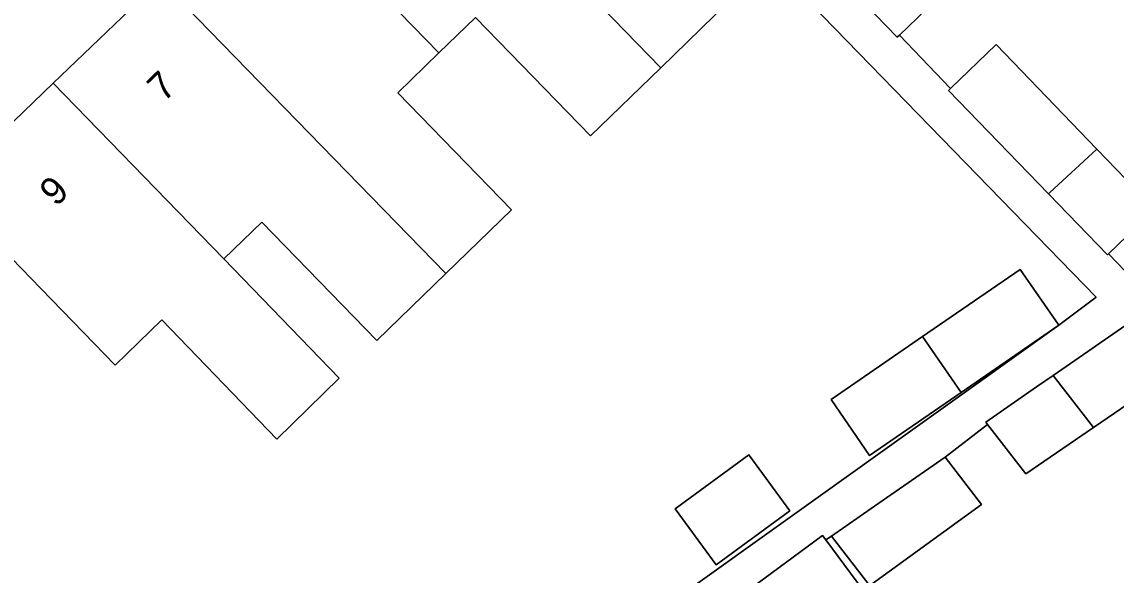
# Model space of a CAD drawing. Extents: x 159716 to 160783, y 383290 to 384031.
# Drawn here: x 160373.24 to 160412.95, y 383590.97 to 383611.06 of the extents above; entities that cross this region are included whole.
import ezdxf

# ---------------------------------------------------------------- set-up
doc = ezdxf.new("R2010")
doc.units = 0
for name, color, linetype in [('IMGEO_Erf', 7, 'Continuous'), ('IMGEO_Pand', 7, 'Continuous'), ('IMGEO_Pand_nummerreeks', 7, 'Continuous'), ('IMGEO_Voetpad_open', 7, 'Continuous')]:
    doc.layers.add(name, color=color, linetype=linetype)

msp = doc.modelspace()

# ---------------------------------------------------------------- linework, layer by layer
at = {"layer": 'IMGEO_Erf'}
for points in [[(160413.12, 383633.736), (160408.508, 383629.478), (160407.851, 383630.189), (160406.37, 383631.793), (160404.46, 383633.863), (160409.273, 383638.305), (160407.196, 383640.387), (160391.191, 383625.117), (160395.117, 383621.009), (160396.709, 383622.544), (160398.982, 383620.189), (160397.38, 383618.642), (160398.946, 383617.003), (160400.557, 383618.557), (160404.398, 383614.578), (160406.727, 383612.166), (160405.085, 383610.58), (160406.942, 383608.637), (160408.595, 383610.231), (160412.256, 383606.439), (160414.358, 383604.26), (160412.676, 383602.637), (160413.594, 383601.677)], [(160382.805, 383579.972), (160410.87, 383600.045), (160412.23, 383601.067), (160396.267, 383617.485), (160394.739, 383615.995), (160398.86, 383611.757), (160396.431, 383609.395), (160393.88, 383606.915), (160389.7, 383611.214), (160388.378, 383609.929), (160386.887, 383608.478), (160391.009, 383604.238), (160388.628, 383601.923), (160386.126, 383599.49), (160381.946, 383603.789), (160380.575, 383602.456), (160384.759, 383598.117), (160382.49, 383595.911), (160378.318, 383600.238), (160376.63, 383598.596), (160373.926, 383601.377), (160370.406, 383605.011)], [(160414.882, 383598.21), (160412.127, 383596.328), (160409.672, 383594.65), (160408.288, 383596.435), (160406.746, 383595.247), (160408.068, 383593.532), (160404.1, 383590.654)], [(160404.385, 383590.097), (160402.62, 383592.385), (160402.421, 383592.247), (160403.755, 383590.432)]]:
    msp.add_lwpolyline(points, dxfattribs=at)
for points in [[(160410.87, 383600.045), (160407.324, 383597.601), (160404.005, 383595.315), (160402.609, 383597.341), (160405.928, 383599.628), (160409.474, 383602.071), (160410.848, 383600.076)], [(160399.621, 383595.332), (160401.109, 383593.306), (160398.442, 383591.348), (160396.954, 383593.374)]]:
    msp.add_lwpolyline(points, close=True, dxfattribs=at)
at = {"layer": 'IMGEO_Pand'}
for points in [[(160396.267, 383617.485), (160393.462, 383620.37), (160390.014, 383623.862), (160386.061, 383620.061), (160396.431, 383609.395), (160398.86, 383611.757), (160394.739, 383615.995)], [(160386.061, 383620.061), (160382.166, 383616.317), (160388.378, 383609.929), (160389.7, 383611.214), (160393.88, 383606.915), (160396.431, 383609.395)], [(160388.378, 383609.929), (160382.166, 383616.317), (160378.272, 383612.574), (160388.628, 383601.923), (160391.009, 383604.238), (160386.887, 383608.478)], [(160404.398, 383614.578), (160402.641, 383612.956), (160405.007, 383610.505), (160405.085, 383610.58), (160406.727, 383612.166)], [(160378.272, 383612.574), (160374.378, 383608.83), (160380.575, 383602.456), (160381.946, 383603.789), (160386.126, 383599.49), (160388.628, 383601.923)], [(160406.942, 383608.637), (160406.874, 383608.571), (160410.498, 383604.817), (160410.548, 383604.864), (160412.256, 383606.439), (160408.595, 383610.231)], [(160380.575, 383602.456), (160374.378, 383608.83), (160370.406, 383605.011), (160373.926, 383601.377), (160376.63, 383598.596), (160378.318, 383600.238), (160382.49, 383595.911), (160384.759, 383598.117)], [(160412.256, 383606.439), (160410.548, 383604.864), (160410.498, 383604.817), (160412.638, 383602.6), (160412.676, 383602.637), (160414.358, 383604.26)], [(160405.928, 383599.628), (160407.324, 383597.601), (160410.87, 383600.045), (160410.848, 383600.076), (160409.474, 383602.071)], [(160410.661, 383598.218), (160412.127, 383596.328), (160414.882, 383598.21), (160413.613, 383600.264)], [(160405.928, 383599.628), (160402.609, 383597.341), (160404.005, 383595.315), (160407.324, 383597.601)], [(160410.661, 383598.218), (160410.059, 383597.801), (160408.218, 383596.525), (160408.288, 383596.435), (160409.672, 383594.65), (160412.127, 383596.328)], [(160401.109, 383593.306), (160399.621, 383595.332), (160396.954, 383593.374), (160398.442, 383591.348)], [(160404.385, 383590.097), (160404.469, 383590.157), (160404.1, 383590.654), (160408.068, 383593.532), (160406.746, 383595.247), (160404.182, 383593.468), (160402.62, 383592.385)], [(160402.421, 383592.247), (160402.302, 383592.409), (160399.654, 383590.464), (160399.721, 383590.373), (160401.107, 383588.487), (160403.755, 383590.432)]]:
    msp.add_lwpolyline(points, close=True, dxfattribs=at)
at = {"layer": 'IMGEO_Voetpad_open'}
for points in [[(160413.594, 383601.677), (160412.676, 383602.637), (160412.638, 383602.6), (160410.498, 383604.817), (160406.874, 383608.571), (160406.942, 383608.637), (160405.085, 383610.58), (160405.007, 383610.505), (160402.641, 383612.956), (160398.837, 383616.897), (160398.946, 383617.003), (160397.38, 383618.642), (160397.262, 383618.528), (160394.988, 383620.884), (160395.117, 383621.009), (160391.191, 383625.117), (160391.123, 383625.052), (160390.014, 383623.862), (160393.462, 383620.37), (160396.267, 383617.485), (160412.23, 383601.067), (160410.87, 383600.045), (160382.805, 383579.972)], [(160342.737, 383596.145), (160347.175, 383597.427), (160351.488, 383598.672), (160355.8, 383599.916), (160360.113, 383601.162), (160364.538, 383602.439), (160369.15, 383603.77), (160370.406, 383605.011), (160374.378, 383608.83), (160378.272, 383612.574), (160382.166, 383616.317), (160386.061, 383620.061), (160390.014, 383623.862)], [(160408.399, 383560.006), (160405.334, 383563.959), (160403.837, 383565.896), (160391.186, 383584.296), (160391.778, 383584.712), (160394.358, 383586.608), (160395.471, 383587.425), (160398.477, 383589.633), (160398.536, 383589.552), (160399.721, 383590.373), (160399.654, 383590.464), (160402.302, 383592.409), (160402.421, 383592.247), (160402.62, 383592.385), (160404.182, 383593.468), (160406.746, 383595.247), (160408.288, 383596.435), (160408.218, 383596.525), (160410.059, 383597.801), (160410.661, 383598.218), (160413.613, 383600.264)]]:
    msp.add_lwpolyline(points, dxfattribs=at)

# ---------------------------------------------------------------- texts
at = {"layer": 'IMGEO_Pand_nummerreeks'}
for s, p in [('7', (160378.391, 383608.116)), ('9', (160374.484, 383604.317))]:
    msp.add_text(s, height=1, rotation=44.1922, dxfattribs=at).set_placement(p)

doc.saveas('drawing.dxf')
